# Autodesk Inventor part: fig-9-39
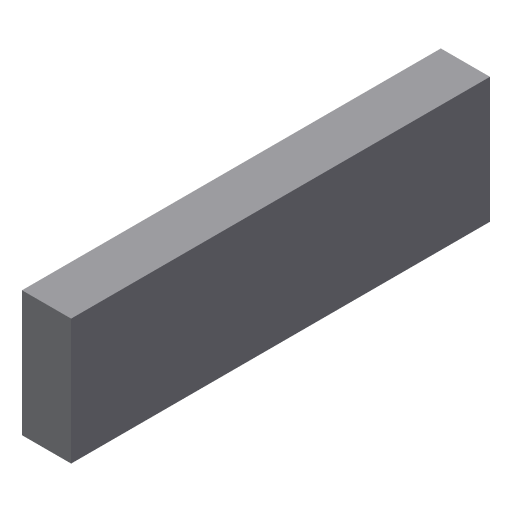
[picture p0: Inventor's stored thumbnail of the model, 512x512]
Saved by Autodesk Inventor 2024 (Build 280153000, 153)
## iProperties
Created: 2013-03
Part Number: fig-9-39
Material: Generic
Document SubType Name: Modeling
Designer: CADCIM
Density: 1 g/cm^3
Appearance: Default
Author: CADCIM
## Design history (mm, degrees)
sketch "Sketch1"
  geometry: L1 (-11.87, 2.655)-(7.31, 2.655); L2 (7.31, 2.655)-(7.31, -3.093); L3 (7.31, -3.093)-(-11.87, -3.093); L4 (-11.87, -3.093)-(-11.87, 2.655); 1 further point
  constraints: 8 end point, 2 parallel, 1 horizontal, 1 perpendicular
extrude "Extrusion1" new body sketch "Sketch1" distance "d0" = 2.25; taper "d1" = 0 deg
body "Solid1"
